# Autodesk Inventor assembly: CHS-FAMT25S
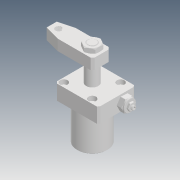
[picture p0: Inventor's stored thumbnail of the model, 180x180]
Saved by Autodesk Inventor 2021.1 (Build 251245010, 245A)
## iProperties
Created: 2019-05
Part Number: CHS-FAMT25S
Description: STEP AP203
Document SubType Name: Assembly
Designer: user
Title: chs-famt25s_asm.STEP
Revision Number: ÈÎºÎ
Sending System: SolidWorks 2017
Preprocessor: SwSTEP 2.0
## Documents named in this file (8)
- D:\Vault_2016\Projekty\Clamptek\Hydraulic\CHS\CHS-25\Inventor\CHS-FAMT25S\CHS-FAMT25S.iam
- D:\Vault_2016\Projekty\Clamptek\Hydraulic\CHS\CHS-25\Inventor\CHS-FAMT25S\CHS-25S-02_2.ipt
- D:\Vault_2016\Projekty\Clamptek\Hydraulic\CHS\CHS-25\Inventor\CHS-FAMT25S\CHS-25S-01_2.ipt
- D:\Vault_2016\Projekty\Clamptek\Hydraulic\CHS\CHS-25\Inventor\CHS-FAMT25S\M14_2.ipt
- D:\Vault_2016\Projekty\Clamptek\Hydraulic\CHS\CHS-25\Inventor\CHS-FAMT25S\CHS-FAMT25BT.ipt
- D:\Vault_2016\Projekty\Clamptek\Hydraulic\CHS\CHS-25\Inventor\CHS-FAMT25S\20·§Ìå.ipt
- D:\Vault_2016\Projekty\Clamptek\Hydraulic\CHS\CHS-25\Inventor\CHS-FAMT25S\20µ÷ËÙ¸Ë.ipt
- D:\Vault_2016\Projekty\Clamptek\Hydraulic\CHS\CHS-25\Inventor\CHS-FAMT25S\hex thin nuts-grades ab-chamfered gb(GB_FASTENER_NUT_STNAB M6-S).ipt
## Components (7 placed, 7 different names)
1. CHS-25S-02_2_1
2. CHS-25S-01_2_2
3. M14_2_3
4. CHS-FAMT25BT_4
5. 20·§Ìå_5
6. 20µ÷ËÙ¸Ë_6
7. hex thin nuts-grades ab-chamfered gb(GB_FASTENER_NUT_STNAB M6-S)_7
